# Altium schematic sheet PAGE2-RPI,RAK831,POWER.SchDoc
size A3
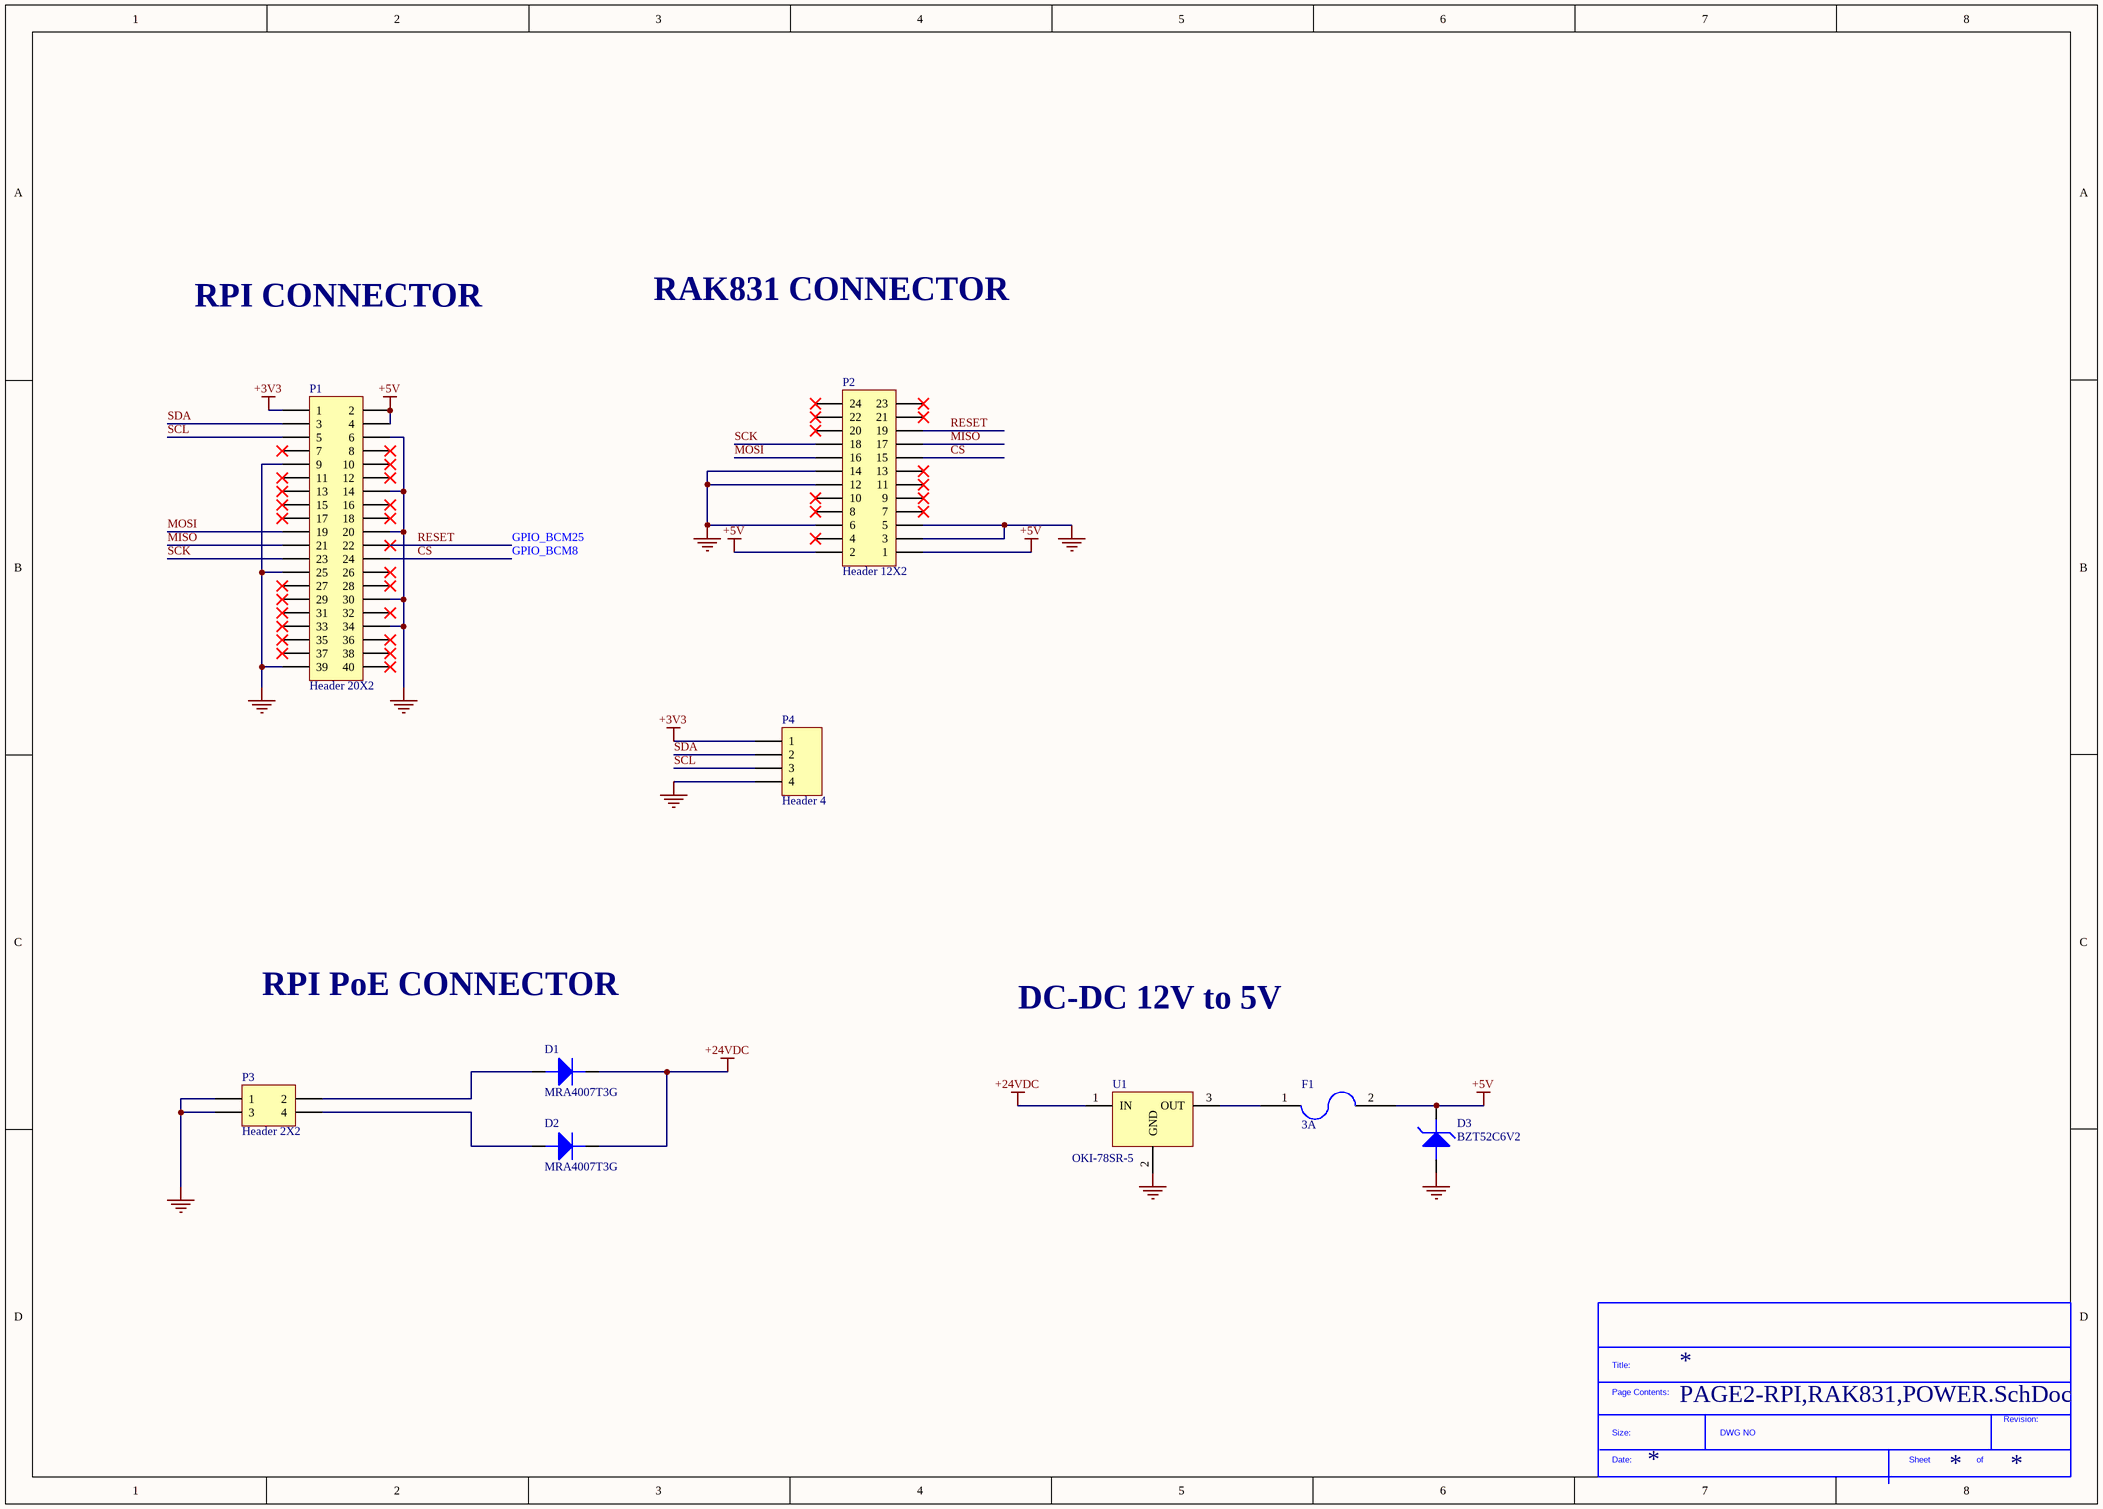
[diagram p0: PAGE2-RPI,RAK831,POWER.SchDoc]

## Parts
*?  SDTitleBlock  (value not drawn)  (graphical)
D1  MRA4007T3G  [DIOM4326X24N_1]
D2  MRA4007T3G  [DIOM4326X24N_1]
D3  BZT52C6V2  [SOD123]
F1  3A  [Chip2PinSM127P600-8N]
P1  Header 20X2  [HDR2X20]  (no BOM)
P2  Header 12X2  [HDR2X12]
P3  Header 2X2  [HDR2X2]
P4  Header 4  [HDR1X4]
U1  OKI-78SR-5  [DC-DC]

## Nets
+3V3: P1.1 P4.1
+5V: D3.1(cathode) F1.2 P1.2 P1.4 P2.1 P2.2
+24VDC: D1.1(cathode) D2.1(cathode) U1.1(IN)
GND: D3.2(ANODE) P1.6 P1.9 P1.14 P1.20 P1.25 P1.30 P1.34 P1.39 P2.3 P2.5 P2.6 P2.12 P2.14 P3.1 P3.3 P4.4 U1.2(GND)
~{CS}: P1.24 P2.15
MISO: P1.21 P2.17
MOSI: P1.19 P2.16
RESET: P1.22 P2.19
SCK: P1.23 P2.18
SCL: P1.5 P4.3
SDA: P1.3 P4.2
NetD1_2: D1.2(ANODE) P3.2
NetD2_2: D2.2(ANODE) P3.4
NetF1_1: F1.1 U1.3(OUT)

Not connected (* = marked no-connect by the designer): P1 7* 8* 10* 11* 12* 13* 15* 16* 17* 18* 26* 27* 28* 29* 31* 32* 33* 35* 36* 37* 38* 40*; P2 4* 7* 8* 9* 10* 11* 13* 20* 21* 22* 23* 24*

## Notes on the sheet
- RPI CONNECTOR
- RAK831 CONNECTOR
- GPIO_BCM25
- GPIO_BCM8
- RPI PoE CONNECTOR
- DC-DC 12V to 5V

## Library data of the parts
D1 D2 = MRA4007T3G: ON SEMICONDUCTOR - MRA4007T3G - DIODE, STANDARD, 1A, 1KV, SMA
D3 = BZT52C6V2: DIODES INC. - BZT52C6V2 - DIODE, ZENER, 6.2V, 0.5W, SOD-123; Zener Voltage Vz Typ: 6.2; Power Dissipation Pd: 500; Zener Tolerance ±: 6%; No. of Pins: 2; Product Range: BZT52 Series; SVHC: No SVHC (12-Jan-2017)
F1 = PTC FUSE 3A: LITTELFUSE - MINISMDC150F/24-2 - POLYSWITCH, SMD, 1812, 1.5A
P1 = Header 20X2: Header, 20-Pin, Dual row
P2 = Header 12X2: Header, 12-Pin, Dual row
P3 = Header 2X2: Header, 2-Pin, Dual row
P4 = Header 4: Header, 4-Pin
U1 = OKI-78SR-5/1.5-W36H-C: Non-Isolated DC/DC Converters 7.5W 24V 5Vout 1.5A Horizontal Mount; Manufacturer: Murata; Min Input Voltage: 7V; Number of Outputs: 1; Output Voltage: 5V; Efficiency: 90.5%; Max Input Voltage: 36V; Max Power Dissipation: 8W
